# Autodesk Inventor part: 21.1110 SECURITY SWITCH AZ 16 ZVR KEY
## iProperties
Created: 2007-05
Part Number: 21.1110 SECURITY SWITCH AZ 16 ZVR KEY
Material: Steel
Document SubType Name: Modeling
Designer: Andy Moles
Density: 7.85 g/cm^3
Author: Andy Moles
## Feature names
1. Base1
